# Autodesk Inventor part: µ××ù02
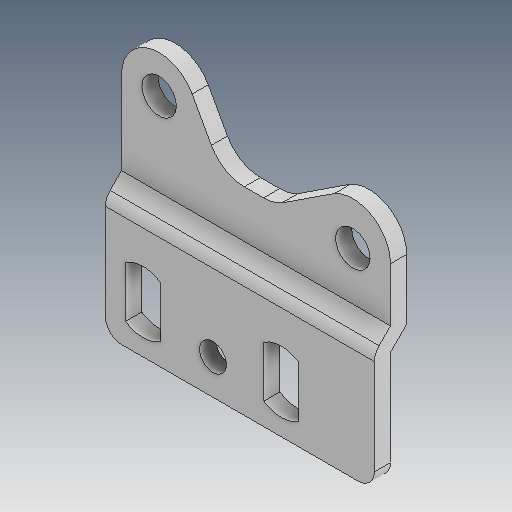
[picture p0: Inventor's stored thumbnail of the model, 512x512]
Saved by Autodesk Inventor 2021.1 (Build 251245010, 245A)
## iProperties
Created: 2020-03
Part Number: µ××ù02
Material: Ogólny
Document SubType Name: Modeling
Designer: user
Density: 1 g/cm^3
Appearance: Domyślna
Author: user
Revision Number: ÈÎºÎ
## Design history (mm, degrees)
feature "ÇÐ³ý-À­Éì2"
node "Bryła1"
